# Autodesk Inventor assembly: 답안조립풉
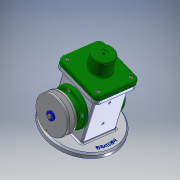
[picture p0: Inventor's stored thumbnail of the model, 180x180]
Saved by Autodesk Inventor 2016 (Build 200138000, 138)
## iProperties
Created: 2019-08
Part Number: 답안조립풉
Material: 일반
Document SubType Name: Assembly
Designer: 3sil_0101
Author: 3sil_0101
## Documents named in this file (18)
- C:\Users\3sil_0101\Desktop\490804V1043\답안조립풉.iam
- C:\Users\3sil_0101\Desktop\490804V1043\본체.ipt
- C:\Users\3sil_0101\Desktop\490804V1043\E-링.ipt
- C:\Users\3sil_0101\Desktop\490804V1043\V-벨트풀리.ipt
- C:\Users\3sil_0101\Desktop\490804V1043\덮개.ipt
- C:\Users\3sil_0101\Desktop\490804V1043\뒤커버.ipt
- C:\Users\3sil_0101\Desktop\490804V1043\링크.ipt
- C:\Users\3sil_0101\Desktop\490804V1043\베어링 17 x 40 x 12.ipt
- C:\Users\3sil_0101\Desktop\490804V1043\볼트 M4 x 8.ipt
- C:\Users\3sil_0101\Desktop\490804V1043\볼트 M4 x 10.ipt
- C:\Users\3sil_0101\Desktop\490804V1043\슬라이더.ipt
- C:\Users\3sil_0101\Desktop\490804V1043\앞커버.ipt
- C:\Users\3sil_0101\Desktop\490804V1043\오일 실 17 30 8.ipt
- C:\Users\3sil_0101\Desktop\490804V1043\와셔 4x16.ipt
- C:\Users\3sil_0101\Desktop\490804V1043\클레비스 핀 6 x 22.ipt
- 클레비스 핀 6 x 22.ipt
- C:\Users\3sil_0101\Desktop\490804V1043\키 4 x 4 x 12.ipt
- C:\Users\3sil_0101\Desktop\490804V1043\편심축.ipt
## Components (2 placed, 2 different names)
1. E-링:1
2. V-벨트풀리:1 — 각도:4
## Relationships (1: Angle 1)
- 각도:4 [Angle]: V-벨트풀리:1
